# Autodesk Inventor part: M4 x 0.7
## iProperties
IsCustomPart: 0
Created: 2009-02
Part Number: M4 x 0.7
Material: 강, 연강
Description: 6각머리 태핑 나사
Document SubType Name: Modeling
Standard: KS B 1003
Designer: SeoGD™
Standards Organization: KS
Language: ko-KR
Size Designation: M 4 x 25
Categories: <MemberInstance><Categories><Category DisplayName="조임쇠" InternalName="e4da775c-781d-43d5-af7c-5136215cf5a6" Mnemonic="FSTN"><Category DisplayName="볼트" InternalN
Density: 1 g/cm^3
Author: SeoGD™
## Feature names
1. Fillet2
